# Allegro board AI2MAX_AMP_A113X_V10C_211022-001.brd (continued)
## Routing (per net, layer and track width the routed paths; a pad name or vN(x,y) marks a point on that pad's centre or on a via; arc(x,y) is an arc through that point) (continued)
NRST_AMP2: length 69.2
  TOP w0.1: v1(29.88,22.52) 29.27,23.12 29.27,27.02 29.6,27.35 29.6,36.5 29.15,36.95 29.15,39.65 v1(29.35,39.85) 29.15,40.05 29.15,46.95 29.6,47.4 v1(29.6,61.75)
  BOTTOM w0.1: v1(29.88,22.52) 30.18,22.52 32.66,25 34.9,25 36.35,26.45 38.5,26.45 R338.2 R315.2 R316.2
  BOTTOM w0.2: U302.36 26.87,58.72 27,58.85 27,59.67 27.42,60.09 C326.2 28.19,60.09 28.35,60.25 28.35,61.4 28.7,61.75 v1(29.6,61.75) ; U301.36 26.87,36.77 27,36.9 27,37.71 C304.2 28.19,38.14 28.35,38.3 28.35,39.4 28.8,39.85 v1(29.35,39.85)
OUT1A_B_LF: length 14
  TOP w0.5: v1(104.8,30.85) v1(104.2,30.85) ; v1(104.8,30.85) 104.8,27.7 ; v1(104.8,30.85) v1(104.8,31.45) 104.5,31.45 ; v1(104.2,30.85) 104.2,28.3 104.5,28 ; v1(104.2,30.85) v1(104.2,31.45) 104.5,31.45 ; 104.8,27.7 104.5,28 ; 104.8,27.7 105.9,26.6 ; 104.5,28 104.5,31.45
OUT1A_B_LW: length 16.6
  TOP w0.4: L211.2 L201.2
  TOP w0.5: 104.5,50 104.8,49.7 ; 104.5,50 104.2,50.3 v1(104.2,52.85) v1(104.2,53.45) 104.5,53.45 ; 104.5,50 104.5,53.45 ; 104.8,49.7 105.9,48.6 ; 104.8,49.7 v1(104.8,52.85) v1(104.8,53.45) 104.5,53.45
  BOTTOM w0.5: 102.9,52.2 C213.1 102.95,53.45
OUT1A_B_RF: length 13.3
  TOP w0.5: 12.2,57.47 v1(12.2,54.3) v1(12.2,53.7) 12.5,53.7 ; 12.2,57.47 11.15,58.52 ; 12.2,57.47 12.5,57.17 ; 12.5,53.7 v1(12.8,53.7) v1(12.8,54.3) 12.8,56.87 12.5,57.17 ; 12.5,53.7 12.5,57.17
OUT1A_B_RW: length 13.4
  TOP w0.5: 11.15,36.58 12.2,35.53 ; 12.2,35.53 v1(12.2,32.35) v1(12.2,31.75) 12.5,31.75 ; 12.2,35.53 12.5,35.23 ; 12.5,31.75 12.5,35.23 ; 12.5,31.75 v1(12.8,31.75) v1(12.8,32.35) 12.8,34.93 12.5,35.23
OUT2A_B_LF: length 13.3
  TOP w0.5: 104.7,36.4 104.8,36.3 v1(104.8,33.35) v1(104.8,32.75) 104.5,32.75 ; 104.7,36.4 104.5,36.2 ; 104.7,36.4 105.9,37.6 ; 104.5,36.2 104.2,35.9 v1(104.2,33.35) v1(104.2,32.75) 104.5,32.75 ; 104.5,36.2 104.5,32.75
OUT2A_B_LW: length 21.2
  TOP w0.5: 104.8,58.5 v1(104.8,55.35) v1(104.8,54.75) 104.5,54.75 ; 104.8,58.5 104.5,58.2 ; 104.8,58.5 105.9,59.6 ; 104.5,58.2 104.5,54.75 ; 104.5,58.2 104.2,57.9 v1(104.2,55.35) v1(104.2,54.75) 104.5,54.75
  BOTTOM w0.5: R205.1 C216.2 C213.2 102.95,54.75 v1(104.2,54.75) ; R205.1 104.2,55.9 v1(104.2,55.35) v1(104.2,54.75) ; R205.1 105,56 104.8,55.8 v1(104.8,55.35) v1(104.8,54.75) v1(104.2,54.75)
OUT2A_B_RF: length 15.4
  TOP w0.4: L304.2 L314.2
  TOP w0.5: 12.5,52.4 v1(12.2,52.4) v1(12.2,51.8) 12.2,48.6 ; 12.5,52.4 12.5,48.9 ; 12.5,52.4 v1(12.8,52.4) v1(12.8,51.8) 12.8,49.2 12.5,48.9 ; 12.5,48.9 12.2,48.6 ; 12.2,48.6 11.15,47.55
OUT2A_B_RW: length 13.4
  TOP w0.5: 12.5,30.45 v1(12.2,30.45) v1(12.2,29.85) 12.2,26.65 ; 12.5,30.45 12.5,26.95 ; 12.5,30.45 v1(12.8,30.45) v1(12.8,29.85) 12.8,27.25 12.5,26.95 ; 12.5,26.95 12.2,26.65 ; 11.15,25.6 12.2,26.65
PDM_DCLK: length 8.5
  TOP w0.1: U1.E16 67.86,48.49 68.4,48.49 68.58,48.31 73.15,48.31 73.49,48.65 74.8,48.65 T102.1
PDM_DIN0: length 9
  TOP w0.1: T103.1 75.85,48.45 73.65,48.45 73.3,48.1 68.49,48.1 68.42,48.17 U1.E17
PDM_DIN1: length 5.9
  TOP w0.1: T104.1 72.37,48.72 68.85,48.72 68.42,49.15 67.87,49.15 U1.D16
PDM_DIN2: length 6.4
  TOP w0.1: T105.1 73.75,49.25 73.01,48.51 68.73,48.51 68.43,48.82 U1.D17
PDM_DIN3: length 3.8
  TOP w0.1: U1.C17 68.46,49.47 68.98,48.95 71.3,48.95 T106.1
POWERSTB: length 67.2
  TOP w0.1: v1(36.75,58.05) 36.75,57.65 36.65,57.55 36.65,36.4 v1(36.85,36.2) ; v1(64.75,59.65) 65.15,59.25 65.15,57.15 v1(65.35,56.95)
  TOP w0.102: v2(64.62,49.15) U1.C12
  BOTTOM w0.1: v1(65.35,56.95) 65.5,56.8 65.5,51.22 64.93,50.65 64.93,49.46 v2(64.62,49.15) ; v1(36.75,58.05) 36.75,57.85 37.15,57.45 46.15,57.45 46.67,57.98 46.67,59.23 46.9,59.45 47.62,59.45 47.92,59.75 50.68,59.75 50.98,59.45 59.15,59.45 59.55,59.85 60.2,59.85 60.8,59.25 64.35,59.25 v1(64.75,59.65)
  BOTTOM w0.3: v1(36.85,36.2) 36.45,35.8 R12.1 R13.1
PVREF: length 0.5
  TOP w0.102: v2(63.97,43.29) U1.N11
PWR_24V: length 187.4
  TOP w0.5: 24.95,57.85 24.9,57.8 24.65,58.05 v1(24.65,58.65) v1(24.65,59.25) 24.95,59.25 ; 24.95,57.85 C355.1 ; 24.95,57.85 24.95,59.25 ; 24.95,57.85 25.25,58.15 v1(25.25,58.65) v1(25.25,59.25) 24.95,59.25 ; 24.95,46.83 v1(24.65,46.83) v1(24.65,47.43) 24.65,48.15 C348.1 24.95,48.35 ; 24.95,46.83 v1(25.25,46.83) v1(25.25,47.43) 25.25,48.05 24.95,48.35 ; 24.95,46.83 24.95,48.35 ; v1(23.4,17.8) v1(22.8,17.8) v1(22.8,17.2) ; v1(23.4,17.8) v1(22.8,17.2) ; v1(23.4,17.8) v1(24,17.8) ; 24.95,26.35 C354.1 ; 24.95,26.35 25.25,26.05 v1(25.25,25.48) v1(25.25,24.88) 24.95,24.88 ; 24.95,26.35 C324.1 24.65,26.15 v1(24.65,25.48) v1(24.65,24.88) 24.95,24.88 ; 24.95,26.35 24.95,24.88 ; 24.95,37.3 v1(24.65,37.3) v1(24.65,36.7) 24.65,36.05 24.9,35.8 24.95,35.85 ; 24.95,37.3 24.95,35.85 ; 24.95,37.3 v1(25.25,37.3) v1(25.25,36.7) 25.25,36.15 24.95,35.85 ; C248.1 91.8,37.1 v1(91.8,37.72) v1(91.8,38.32) 92.1,38.32 ; C248.1 92.1,38.32 ; C248.1 92.4,37.1 v1(92.4,37.72) v1(92.4,38.32) 92.1,38.32 ; C248.1 C258.1 ; v1(91.8,20.95) v1(92.4,20.95) ; v1(91.8,20.95) v1(92.4,20.35) ; v1(91.8,20.95) v1(91.2,20.95) ; v1(91.8,20.95) v1(91.2,21.55) ; v1(92.4,20.95) v1(91.8,21.55) ; v1(92.4,20.95) v1(92.4,21.55) v1(91.8,21.55) ; v1(92.4,20.95) v1(92.4,20.35) ; 92.1,27.4 91.8,27.1 v1(91.8,26.5) v1(91.8,25.9) 92.1,25.9 ; 92.1,27.4 92.1,25.9 ; 92.1,27.4 C257.1 ; 92.1,27.4 92.4,27.1 v1(92.4,26.5) v1(92.4,25.9) 92.1,25.9 ; 92.1,47.84 v1(91.8,47.84) v1(91.8,48.44) 91.8,49.1 92.1,49.4 ; 92.1,47.84 92.1,49.4 ; 92.1,47.84 v1(92.4,47.84) v1(92.4,48.44) 92.4,49.1 92.1,49.4 ; v1(22.8,17.2) v1(22.8,16.6) ; v1(92.4,20.35) v1(91.8,20.35) ; 24.95,48.35 C356.1 ; v1(22.8,16.6) v1(23.4,17.2) v1(24,17.8) ; v1(22.8,16.6) v1(23.4,16.6) ; v1(91.8,21.55) v1(91.2,21.55) ; 92.1,49.4 C255.1 ; C224.1 91.8,59.1 v1(91.8,59.66) v1(91.8,60.26) 92.1,60.26 ; C224.1 92.4,59.1 v1(92.4,59.66) v1(92.4,60.26) 92.1,60.26 ; C224.1 92.1,60.26 ; C224.1 C256.1 ; 24.95,35.85 C353.1 ; v1(91.2,20.95) v1(91.8,20.35) ; v1(91.2,20.95) v1(91.2,21.55) ; v1(91.2,20.95) v1(91.2,20.35) v1(91.8,20.35) ; v1(23.4,16.6) v1(24,16.6) v1(24,17.2) ; v1(23.4,16.6) v1(24,17.2) ; v1(24,17.8) v1(24,17.2)
  TOP w0.6: C4.1 12.87,10.12 U2.2
  BOTTOM w0.2: R1.2 v1(19.65,17)
  BOTTOM w0.3: 92.1,58.74 92.18,58.66 ; 92.18,58.66 92.18,57.69 ; 92.18,58.66 92.46,58.38 ; 24.6,56.68 24.87,56.68 ; 24.6,56.68 24.38,56.68 ; 24.6,56.68 24.6,57.35 24.59,57.37 ; 24.87,56.68 24.87,57.65 ; 24.87,56.68 U302.32 ; 24.59,57.37 24.87,57.65 ; 24.59,57.37 24.59,58.59 v1(24.65,58.65) ; 24.59,57.37 24.38,57.16 24.38,56.68 ; 24.87,57.65 24.95,57.73 ; 92.46,36.44 92.18,36.72 ; 92.46,36.44 92.67,36.23 92.67,35.75 ; 92.46,36.44 92.46,37.66 v1(92.4,37.72) ; 92.46,36.44 92.45,36.42 92.45,35.75 ; 92.18,36.72 92.18,35.75 ; 92.18,36.72 C248.1 ; 24.38,34.73 24.38,35.21 24.59,35.42 ; 24.38,34.73 24.37,34.72 U301.31 ; 24.38,34.73 24.6,34.73 ; 92.18,57.69 92.45,57.69 ; 92.18,57.69 U201.19 ; 24.59,48.71 24.38,48.92 24.38,49.4 ; 24.59,48.71 24.87,48.43 ; 24.59,48.71 24.59,47.49 v1(24.65,47.43) ; 24.59,48.71 24.6,48.73 24.6,49.4 ; 24.6,34.73 24.87,34.73 ; 24.6,34.73 24.6,35.4 24.59,35.42 ; 24.87,34.73 24.87,35.75 ; 24.87,34.73 U301.32 ; 92.18,49.5 C206.1 ; 92.18,49.5 92.4,49.72 92.46,49.72 ; 92.18,49.5 92.18,50.41 ; 24.95,48.35 C348.1 24.87,48.43 ; 24.6,27.45 24.87,27.45 ; 24.6,27.45 24.6,26.78 24.59,26.76 24.38,26.97 24.38,27.45 ; 24.6,27.45 24.38,27.45 ; 24.87,27.45 U301.19 ; 24.87,27.45 24.87,26.43 C324.1 ; 92.67,57.69 92.45,57.69 ; 92.67,57.69 92.68,57.68 U201.20 ; 92.67,57.69 92.67,58.17 92.46,58.38 ; 92.45,57.69 92.45,58.36 92.46,58.38 ; 92.46,58.38 92.46,59.6 v1(92.4,59.66) ; 24.59,35.42 24.59,35.47 24.87,35.75 ; 92.45,28.47 92.67,28.47 ; 92.45,28.47 92.45,27.8 92.46,27.78 ; 92.45,28.47 92.18,28.47 ; 92.67,28.47 92.67,27.99 92.46,27.78 ; 92.67,28.47 92.68,28.48 U202.31 ; 24.38,27.45 24.37,27.46 U301.20 ; U202.20 92.68,35.74 92.67,35.75 ; v1(92.4,26.5) 92.46,26.56 92.46,27.78 ; 24.6,49.4 24.87,49.4 ; 24.6,49.4 24.38,49.4 ; 24.87,49.4 24.87,48.43 ; 24.87,49.4 U302.19 ; 92.46,49.72 92.67,49.93 92.67,50.41 ; 92.46,49.72 92.45,49.74 92.45,50.41 ; 92.67,35.75 92.45,35.75 ; 92.45,35.75 92.18,35.75 ; 24.38,56.68 24.37,56.67 U302.31 ; 24.38,49.4 24.37,49.41 U302.20 ; 24.87,35.75 C306.1 ; 92.67,50.41 92.68,50.42 U201.31 ; 92.67,50.41 92.45,50.41 ; 92.18,28.47 U202.32 ; 92.18,28.47 92.18,27.5 ; 92.45,50.41 92.18,50.41 ; 92.18,50.41 U201.32 ; 92.46,27.78 92.18,27.5 ; 92.18,27.5 C231.1 ; 92.18,35.75 U202.19
  BOTTOM w0.5: v1(76.9,66.9) v1(77.5,66.3) ; v1(76.9,66.9) v1(76.3,67.5) ; v1(76.9,66.9) v1(76.9,67.5) ; v1(76.9,66.9) v1(76.9,66.3) ; v1(77.5,66.3) v1(77.5,66.9) ; v1(77.5,66.3) v1(77.5,65.7) ; v1(11.5,3.3) v1(11.5,2.7) v1(10.9,2.7) ; v1(11.5,3.3) v1(10.9,2.7) ; v1(11.5,3.3) v1(11.5,3.9) ; v1(24.65,47.43) v1(24.65,46.83) ; v1(24.65,47.43) v1(25.25,47.43) ; v1(24.65,47.43) 24.65,48.05 24.95,48.35 24.95,47.73 v1(25.25,47.43) ; v1(24.65,46.83) v1(25.25,46.83) v1(25.25,47.43) ; v1(24.65,46.83) v1(25.25,47.43) ; v1(10.9,3.3) v1(11.5,3.9) ; v1(10.9,3.3) v1(10.9,3.9) v1(11.5,3.9) ; v1(10.9,3.3) v1(10.9,2.7) ; v1(92.4,60.26) v1(91.8,60.26) v1(91.8,59.66) ; v1(92.4,60.26) v1(92.4,59.66) ; v1(92.4,60.26) v1(91.8,59.66) ; v1(24.65,58.65) v1(24.65,59.25) ; v1(24.65,58.65) v1(25.25,58.65) ; v1(24.65,58.65) 24.65,58.03 C331.1 24.95,57.73 24.95,58.35 v1(25.25,58.65) ; v1(24.65,59.25) v1(25.25,58.65) ; v1(24.65,59.25) v1(25.25,59.25) v1(25.25,58.65) ; v1(92.4,37.72) v1(92.4,38.32) ; v1(92.4,37.72) v1(91.8,37.72) ; v1(92.4,37.72) 92.4,37.1 C248.1 92.1,37.42 v1(91.8,37.72) ; v1(92.4,38.32) v1(91.8,37.72) ; v1(92.4,38.32) v1(91.8,38.32) v1(91.8,37.72) ; 24.65,36.03 C306.1 24.9,36.35 v1(25.25,36.7) ; 24.65,36.03 24.65,34.78 24.6,34.73 ; 24.65,36.03 v1(24.65,36.7) ; 43.8,68.85 v1(44.4,68.85) v1(44.4,68.25) ; 43.8,68.85 v1(44.4,68.25) ; 43.8,68.85 v1(43.75,68.85) v1(43.75,68.25) ; v1(76.3,67.5) v1(76.3,66.9) ; v1(76.3,67.5) v1(76.9,67.5) ; v1(76.9,67.5) v1(77.5,66.9) ; v1(76.9,67.5) v1(77.5,67.5) v1(77.5,66.9) ; v1(91.8,48.44) v1(92.4,48.44) ; v1(91.8,48.44) v1(91.8,47.84) v1(92.4,47.84) ; v1(91.8,48.44) v1(92.4,47.84) ; v1(91.8,48.44) 92.1,48.74 C206.1 ; v1(92.4,48.44) v1(92.4,47.84) ; v1(92.4,48.44) 92.4,49.9 92.45,49.95 ; v1(76.3,66.3) v1(76.9,65.7) ; v1(76.3,66.3) v1(76.3,65.7) ; v1(76.3,66.3) v1(76.3,66.9) ; v1(76.9,65.7) v1(76.9,65.1) ; v1(76.9,65.7) v1(76.9,66.3) ; v1(76.9,65.7) v1(77.5,65.1) ; v1(91.8,59.66) 92.1,59.36 C224.1 92.1,58.74 92.4,59.04 v1(92.4,59.66) ; v1(91.8,59.66) v1(92.4,59.66) ; v1(44.4,68.25) v1(44.4,67.6) ; v1(76.9,65.1) v1(76.3,65.1) v1(76.3,65.7) ; v1(76.9,65.1) v1(77.5,65.1) ; v1(76.9,65.1) v1(76.3,65.7) ; v1(76.9,66.3) v1(77.5,65.7) ; v1(76.9,66.3) v1(76.3,66.9) ; 43.8,67.6 43.75,67.65 v1(43.75,68.25) ; 43.8,67.6 v1(44.4,67.6) ; 43.8,67.6 v1(43.75,67.6) v1(43.75,67) v1(44.4,67) ; 43.8,67.6 v1(44.4,67) ; v1(44.4,67.6) v1(43.75,68.25) ; v1(44.4,67.6) v1(44.4,67) ; v1(77.5,65.1) v1(77.5,65.7) ; v1(25.25,36.7) v1(25.25,37.3) v1(24.65,37.3) ; v1(25.25,36.7) v1(24.65,37.3) ; v1(25.25,36.7) v1(24.65,36.7) ; v1(91.8,26.5) v1(92.4,25.9) ; v1(91.8,26.5) v1(91.8,25.9) v1(92.4,25.9) ; v1(91.8,26.5) 92.1,26.8 C231.1 92.4,27.12 v1(92.4,26.5) ; v1(91.8,26.5) v1(92.4,26.5) ; v1(92.4,25.9) v1(92.4,26.5) ; v1(25.25,25.48) v1(24.65,25.48) ; v1(25.25,25.48) v1(24.65,24.88) ; v1(25.25,25.48) v1(25.25,24.88) v1(24.65,24.88) ; v1(25.25,25.48) 24.95,25.78 24.95,26.35 C324.1 24.65,26.15 ; v1(24.65,25.48) 24.65,26.15 ; v1(24.65,25.48) v1(24.65,24.88) ; v1(24.65,37.3) v1(24.65,36.7) ; 24.65,26.15 24.65,27.05 24.6,27.1
  vias: v1(32.25,3.5) v1(32.25,2.9) v1(32.25,2.3) v1(32.85,3.5) v1(32.85,2.9) v1(32.85,2.3) v1(33.45,3.5) v1(33.45,2.9) v1(33.45,2.3) v1(59.95,5.65) v1(59.95,5.05) v1(59.95,4.45) v1(60.55,5.65) v1(60.55,5.05) v1(60.55,4.45) v1(61.15,5.65) v1(61.15,5.05) v1(61.15,4.45) v1(74.65,13.15) v1(74.65,12.55) v1(74.65,11.95) v1(74.65,11.35) v1(75.25,13.15) v1(75.25,12.55) v1(75.25,11.95) v1(75.25,11.35) v1(75.85,13.15) v1(75.85,12.55) v1(75.85,11.95) v1(75.85,11.35)
RMII_MDC: length 13.2
  TOP w0.1: U1.A11 64.29,50.91 63.96,51.25 63.96,55.05 64.75,55.84 64.75,56.5 64.47,56.77 63.88,56.77 63.7,56.95 63.7,59.95 64.3,60.55 64.8,60.55 v1(65.2,60.95)
  BOTTOM w0.4: v1(65.2,60.95) 66.03,60.95 T322.1
RMII_MDIO: length 15.5
  TOP w0.1: v1(65.9,62.3) 63.9,62.3 62.85,61.25 62.85,59.75 62.25,59.15 62.25,51.26 62.34,51.17 U1.A8
  BOTTOM w0.4: v1(65.9,62.3) 65.9,63.36 T323.1
RMII_RXCLK: length 15.2
  TOP w0.1: v1(61.77,62.48) 61.77,61.12 61.01,60.36 61.01,53.8 61.5,53.3 61.5,51.04 61.36,50.9 61.36,50.45 U1.B7
  BOTTOM w0.1: 62.8,63.5 v1(61.77,62.48)
  BOTTOM w0.4: T325.1 62.8,63.5
RMII_RXD0: length 17
  TOP w0.1: U1.B8 62.01,50.45 62.01,59.21 62.65,59.85 62.65,61.85 63.05,62.25 v1(63.05,62.45)
  BOTTOM w0.1: v1(63.05,62.45) 62.65,62.05 61,62.05 60.5,62.55 60.5,63.04
  BOTTOM w0.4: T327.1 60.5,63.04
RMII_RXD1: length 12.6
  TOP w0.1: U1.A6 61.04,50.94 61.22,51.12 61.22,52.97 60.25,53.95 60.25,60.1 v1(59.4,60.95)
  BOTTOM w0.4: T326.1 59.41,60.96 v1(59.4,60.95)
RMII_RXDV: length 11.3
  TOP w0.1: U1.A7 61.77,50.85 61.77,59.32 62.25,59.8 v1(62.25,60.25)
  BOTTOM w0.4: T324.1 62.96,60.96 v1(62.25,60.25)
RMII_TXD0: length 17.6
  TOP w0.1: v1(64.4,60.95) 63.49,60.04 63.49,51.07 63.64,50.92 U1.A10
  BOTTOM w0.1: 58.89,60.49 60.51,60.49 61.15,59.85 63.45,59.85 64.4,60.8 v1(64.4,60.95)
  BOTTOM w0.4: T328.1 58.89,60.49
RMII_TXD1: length 24.1
  TOP w0.1: v1(65.2,61.75) 64.8,61.35 64,61.35 63.25,60.6 63.25,50.95 63.32,50.88 63.32,49.8 62.99,49.47 U1.C9
  BOTTOM w0.1: v1(65.2,61.75) 64.8,61.35 64.25,61.35 63.95,61.65 60.2,61.65 59.85,62 57.38,62 56.72,62.66
  BOTTOM w0.4: T331.1 56.72,62.66
RMII_TXEN: length 20.2
  TOP w0.1: v1(64.4,61.75) 63.8,61.75 63.05,61 63.05,59.65 62.48,59.08 62.48,51.41 62.66,51.23 62.66,50.45 U1.B9
  BOTTOM w0.1: v1(64.4,61.75) 64.3,61.85 60.35,61.85 59.95,62.25 58.8,62.25 58.42,62.63
  BOTTOM w0.4: T329.1 58.42,62.63
SCL: length 8.3
  BOTTOM w0.1: J813.8 83.68,8.92 82.2,10.4 80.95,10.4 80.45,10.9 80.45,13.3 80.9,13.75 UNK5R66.1
SCL_AMP1: length 66.9
  TOP w0.1: R349.2 85.5,59.2 v1(85.35,59.05) 85.35,58.45 86,57.8 86,47.9 86.3,47.6 86.3,37.4 v1(85.95,37.05)
  BOTTOM w0.1: v1(85.35,59.05) 81.95,59.05 81.5,58.6 79.15,58.6 R238.2 78.25,58.6 73,58.6 72.8,58.8 67.6,58.8 67.05,59.35 66.47,59.35 65.77,58.65 64.6,58.65 64.4,58.85 52.95,58.85 51.85,57.75 R211.2
  BOTTOM w0.2: U201.11 88.18,57.2 87.4,57.2 87.15,57.45 87.15,58.43 C222.2 87.07,58.48 86.5,59.05 v1(85.35,59.05) ; v1(85.95,37.05) 86.68,37.05 C246.2 87.2,35.55 87.4,35.35 88.05,35.35 88.18,35.22 U202.11
SCL_AMP2: length 59.8
  TOP w0.1: v1(31.4,57.4) 31,57 31,56.6 31.2,56.4 31.2,48.55 v1(31.05,48.4) 31.25,48.2 31.25,39.35 30.85,38.95 30.85,37.4 31.25,37 31.25,26.3 v1(31.1,26.15) 31.3,25.95 R351.2 ; R309.2 v1(48.2,57.7)
  BOTTOM w0.1: v1(31.05,48.4) 30.06,48.4 C346.2 29.85,49.48 29.48,49.85 28.87,49.85 U302.11 ; R311.2 v1(48.2,57.7) 47.15,56.65 36.65,56.65 35.85,55.85 33.4,55.85 32.25,57 31.8,57 v1(31.4,57.4)
  BOTTOM w0.2: v1(31.1,26.15) 30.59,26.66 C322.2 29.85,27.5 29.4,27.95 28.87,27.95 U301.11
SDA: length 5.2
  BOTTOM w0.1: J813.7 84.18,8.72 82.3,10.6 81.15,10.6 80.9,10.85 UNK5R65.1
SDA_AMP1: length 69.4
  TOP w0.1: v1(85.35,35.95) 85.35,37.05 86.1,37.8 86.1,47.5 85.8,47.8 85.8,57.44 v1(85.35,57.89) 84.95,58.29 84.95,59.25 85.25,59.55 85.4,59.55 R348.2
  BOTTOM w0.1: v1(85.35,57.89) 85.35,58.25 84.75,58.85 82.1,58.85 81.65,58.4 79.15,58.4 R239.2 78.25,58.4 72.9,58.4 72.7,58.6 67.5,58.6 66.95,59.15 66.55,59.15 65.85,58.45 64.5,58.45 64.3,58.65 53.05,58.65 52.5,58.1 52.5,57.25 R212.2
  BOTTOM w0.2: U201.10 86.02,56.3 C217.2 85.35,56.85 v1(85.35,57.89) ; v1(85.35,35.95) 85.35,34.91 C241.2 86.02,34.36 U202.10
SDA_AMP2: length 58.3
  TOP w0.1: v1(48.2,56.6) R310.2 ; v1(31.4,56.8) 31.4,49.45 v1(31.65,49.2) 31.45,49 31.45,39.25 31.05,38.85 31.05,37.5 31.45,37.1 31.45,27.5 v1(31.7,27.25) 31.7,26.15 R350.2
  BOTTOM w0.1: v1(31.65,49.2) 31.65,50.28 C341.2 31.04,50.79 U302.10 ; R312.2 v1(48.2,56.6) 48.05,56.45 36.75,56.45 35.95,55.65 33.3,55.65 32.15,56.8 v1(31.4,56.8)
  BOTTOM w0.2: v1(31.7,27.25) 31.7,28.29 C317.2 31.03,28.84 U301.10
SPDIF_IN: length 7.2
  TOP w0.102: v2(66.57,48.5) U1.E14
  BOTTOM w0.1: T107.1 72.43,49.68 70.48,49.68 69.95,49.15 67.8,49.15 67.43,48.78 66.85,48.78 v2(66.57,48.5)
SPDIF_OUT: length 3.1
  TOP w0.102: U1.C16 67.87,49.8 68.45,49.8 68.62,49.63 T108.1
SPI_CLK: length 33.2
  TOP w0.102: v1(52.83,54.36) 52.53,54.66 v1(52.53,60.35) ; U1.C6 61.38,49.8 v2(61.36,49.8)
  BOTTOM w0.1: v1(52.53,60.35) 39.25,60.35 38.8,60.8 ; v1(52.83,54.36) 58.69,54.36 61.21,51.84 61.21,50.05 61.36,49.9 v2(61.36,49.8)
  BOTTOM w0.3: UNK2T16.1 38.8,60.8
SPI_MISO: length 33.4
  TOP w0.1: v1(50.95,60.95) 51.51,60.39 51.51,59.54
  TOP w0.102: v1(52.05,53.55) 51.51,54.09 51.51,59.54 ; U1.D6 60.71,49.15 v2(60.71,49.15)
  BOTTOM w0.1: v1(50.95,60.95) 50.75,60.75 41.55,60.75 41.2,61.1 41.2,62.8 ; v2(60.71,49.15) 61.01,49.44 61.01,51.53 59.14,53.39 53.46,53.39 53.3,53.55 v1(52.05,53.55)
  BOTTOM w0.3: UNK2T19.1 41.2,62.8
SPI_MOSI: length 31.6
  TOP w0.1: 51.95,53.95 52.2,53.95 52.6,53.55 v1(52.6,53.15)
  TOP w0.102: v1(51.55,60.95) 51.71,60.79 51.71,54.19 51.95,53.95 ; U1.C5 60.65,49.73 v2(60.65,49.74)
  BOTTOM w0.1: v1(51.55,60.95) 51.15,60.55 41.05,60.55 40.71,60.89 ; v1(52.6,53.15) 59.07,53.15 60.81,51.41 60.81,49.89 v2(60.65,49.74)
  BOTTOM w0.3: UNK2T18.1 40.71,60.89
SPI_SS0: length 28.1
  TOP w0.1: U1.C1 57.64,49.47 56.79,50.32 56.79,50.9 55.37,52.33 55.37,53.14 54.6,53.91 54.6,57.1 54.26,57.44 54.26,62.43 53.7,62.99 v1(53.7,63.1)
  BOTTOM w0.1: v1(53.7,63.1) 53.3,63.5 52.7,63.5 51.9,62.7 43.1,62.7 42.8,62.4
  BOTTOM w0.3: UNK2T20.1 42.8,62.4
SPK_I2C_SCK: length 24.1
  TOP w0.1: v1(48.95,61.9) 49.85,61 49.85,59.8 50.35,59.3 v1(50.35,57.7) 49.95,57.3 49.95,56.4 50.55,55.8 50.55,53.05 51.35,52.25 53.9,52.25 54.53,51.62 55.16,51.62 56.18,50.6 56.18,49.99 57.68,48.49 58.77,48.49 U1.E3
  BOTTOM w0.1: R211.1 v1(50.35,57.7) R311.1 UNK2R18.2
  BOTTOM w0.3: UNK2T26.1 48.65,61.6 v1(48.95,61.9)
SPK_I2C_SDA: length 23.4
  TOP w0.1: v1(50.7,63.3) 50.05,62.65 50.05,59.9 50.75,59.2 50.75,57 v1(50.35,56.6) 50.77,56.18 50.77,53.14 51.45,52.45 54,52.45 54.61,51.84 55.25,51.84 56.39,50.7 56.39,50.09 57.66,48.82 U1.D1
  BOTTOM w0.1: R212.1 v1(50.35,56.6) R312.1 UNK2R19.2
  BOTTOM w0.3: v1(50.7,63.3) 50.3,63.3 UNK2T27.1
SPK_RST: length 13.9
  TOP w0.102: U1.C15 67.21,49.79 67.21,50.27 67.38,50.45 67.71,50.45 67.87,50.6 67.87,51.72 70.71,54.56 72.5,54.56 v2(72.62,54.68) ; v2(70.86,56.95) 70.86,57.76 71.53,58.42 UNK2T8.1
  BOTTOM w0.1: v2(70.86,56.95) 72.62,55.2 v2(72.62,54.68)
STANDBY_A113X: length 66.3
  TOP w0.1: v1(66.75,56.95) v2(66.75,58.78) ; v1(81.9,54.5) 82.25,54.15 82.25,48.55 82.5,48.3 82.5,33.75 83.3,32.95 83.3,20.95 v1(83.75,20.5)
  TOP w0.102: U1.C13 65.59,49.47 v2(65.3,49.76)
  BOTTOM w0.1: v1(66.75,56.95) 66.7,56.95 65.73,55.98 65.73,50.99 65.3,50.56 v2(65.3,49.76) ; UNK5R77.2 82,18.55 82.75,19.3 83.8,19.3 84.15,19.65 84.15,20.1 v1(83.75,20.5) ; v1(81.9,54.5) 80.8,55.6 74.4,55.6 71.6,58.4 67.13,58.4 v2(66.75,58.78)
SYS_LED: length 20.7
  TOP w0.1: v1(64.7,63.5) UNK2R8.2
  TOP w0.102: U1.A15 66.95,50.83 66.95,51.72 68.88,53.65 68.88,54.76 70.45,56.33 70.45,57.96 70.87,58.37 70.87,60.5 69.75,61.62 v1(69.75,62)
  BOTTOM w0.3: v1(69.75,62) 69.45,62.3 68.5,62.3 66.45,64.35 65.55,64.35 v1(64.7,63.5)
USB_PWR_EN: length 16.4
  TOP w0.102: UNK2T7.1 70.2,60.1 69.64,59.54 69.64,57.66 v2(69.8,57.51) ; v2(64.56,49.75) 64.55,49.74 64.55,49.73 U1.C11
  BOTTOM w0.1: v2(64.56,49.75) 64.56,51.49 64.95,51.87 64.95,54.85 64.65,55.15 64.65,55.5 64.97,55.83 64.97,57.48 65.17,57.67 69.63,57.67 v2(69.8,57.51)
USB_TXRTUNE: length 5.4
  TOP w0.102: v2(66.57,45.24) 66.57,45.25 U1.J15
  BOTTOM w0.1: v2(66.57,45.24) 66.89,45.57 68.81,45.57 68.96,45.72 69.67,45.72 69.85,45.54 69.85,45.39 UNK5R64.1
USBOTG_A_DM: length 45.2
  TOP w0.1: U1.L16 67.77,44.27 68.09,43.95 68.96,43.95 69.39,43.52 69.72,43.52 70.88,42.37 70.88,41.06 72.38,39.56 72.38,37.46 73.15,36.68 73.15,22.7 77.8,18.05 80.16,18.05 81.64,16.57 84.42,16.57 v1(84.65,16.35) 85.1,16.35 UNK5R84.2
  BOTTOM w0.1: v1(84.65,16.35) 85.55,15.45 UNK5D12.1 85.55,14.15 85.45,14.05 84.85,14.05 84.75,13.95 84.75,13.55 85.15,13.15 85.15,12.55 85.55,12.15 UNK5R71.2
USBOTG_A_DP: length 45.3
  TOP w0.1: U1.L17 68.28,44.17 69.06,44.17 69.48,43.75 69.82,43.75 71.1,42.47 71.1,41.15 72.6,39.65 72.6,37.55 73.38,36.77 73.38,22.79 77.89,18.27 80.26,18.27 81.73,16.8 84.35,16.8 v1(84.65,17.1) 85.05,17.1 UNK5R85.2
  BOTTOM w0.1: v1(84.65,17.1) 84.2,16.65 84.2,15 83.75,14.55 UNK5D11.1 83.75,14.15 83.85,14.05 84.45,14.05 84.53,13.97 84.53,13.46 84.92,13.06 84.92,12.52 84.55,12.15 UNK5R72.2
USBOTG_A_ID: length 39.4
  TOP w0.1: UNK5R83.2 81.95,18.2 v1(81.55,18.6) 80.8,19.35 78.35,19.35 75.1,22.6 75.1,29.35 75.85,30.1 75.85,39 v1(74.15,40.7) UNK5R78.1 UNK5C3.2 73.95,42.55 73.35,43.15 73.35,43.8 72.88,44.27 69.7,44.27 69.29,44.68 68.61,44.68 68.37,44.92 U1.K17
  BOTTOM w0.1: v1(81.55,18.6) 80.9,17.95 UNK5R76.2
  BOTTOM w0.3: UNK5R20.2 74.4,40.7 v1(74.15,40.7)
USBOTG_A_VBUS: length 7
  TOP w0.1: U1.K16 67.86,44.6 68.35,44.6 68.51,44.44 69.17,44.44 69.57,44.05 72.2,44.05 UNK5C11.2
  TOP w0.3: UNK5R5.2 UNK5C11.2
WPN: length 3.3
  TOP w0.1: v1(47.15,30.2) 47.14,30.21 UNK4U5.19
  BOTTOM w0.1: v1(47.15,30.2) UNK4C9.2 UNK4R4.2
N21450221: length 2.7
  BOTTOM w0.3: Q1.1 34.2,32.35 C23.1 R13.2
N21455517: length 0.8
  TOP w0.3: U1.F13 v2(65.27,47.2)
  BOTTOM w0.2: v2(65.27,47.2) 65.05,46.98 UNK2R27.1
N21455804: length 4.3
  TOP w0.102: v2(67.14,48.43) 67.14,48.42 U1.E15
  BOTTOM w0.3: UNK2R29.1 70.5,48.75 67.85,48.75 67.53,48.43 v2(67.14,48.43)
N21455846: length 2.7
  TOP w0.1: UNK2R12.2 59.55,61.95 UNK2Q1.3
N21455854: length 1.8
  TOP w0.1: UNK2D7.2 56.1,62.85 UNK2R12.1
N21456017: length 6.3
  TOP w0.102: U1.D11 63.98,49.15 v2(63.97,49.15)
  BOTTOM w0.1: UNK2T29.1 63.24,53.69 63.24,52.29 63.93,51.6 63.93,50.4 63.6,50.07 63.6,49.36 63.82,49.15 v2(63.97,49.15)
N21456060: length 7.4
  TOP w0.127: 68.4,50.47 68.38,50.45 68.05,50.45 67.72,50.12 U1.B16
  TOP w0.2: UNK2Y2.1 73.14,50.4 71.9,50.4 71.36,50.94 UNK2C3.2 71.28,51.06 UNK2R5.1 69.59,50.47 68.4,50.47
N21456068: length 4.4
  TOP w0.2: UNK2R10.2 70.48,53.21 69.52,52.25 69.52,51.14 69.23,50.85 68.27,50.85 U1.A17
N21456125: length 7.6
  TOP w0.2: UNK2Y2.3 75.17,53.95 73.26,53.95 72.52,53.21 UNK2R10.1 71.85,52.61 UNK2C9.2 70.34,52.12 UNK2R5.2
N21456352: length 6.9
  TOP w0.1: UNK2R1.1 59.96,68.99 UNK2CON1.4
N21456391: length 6.4
  TOP w0.1: UNK2CON1.2 58.84,70.05 UNK2R16.1
N21464427: length 1
  TOP w0.102: U1.N8 62.6,43.23 v2(62.6,43.23)
  BOTTOM w0.102: v2(62.6,43.23) 62.84,43.23 UNK3R6.2
N21467829: length 7.5
  TOP w0.1: U1.M3 59.09,43.62 v2(58.76,43.94)
  BOTTOM w0.102: UNK4T25.1 53.4,41.1 54,41.1 54.7,41.8 55.4,41.8 56.71,43.11 57.46,43.11 58.29,43.94 v2(58.76,43.94)
N21468142: length 76.3
  TOP w0.1: v1(38.15,27.05) 37.65,27.05 36.85,27.85 36.85,33.6 37.5,34.25 37.5,36.45 37.05,36.9 37.05,52.45 v1(37.25,52.65) ; v1(39.45,54) 39.58,54 UNK4R10.1 ; v1(8.7,16.1) 8.7,14.32 7.47,13.1 UNK4K2.4 UNK4K2.3
  BOTTOM w0.1: v1(37.25,52.65) 37.25,52.8 38.45,54 v1(39.45,54) ; v1(38.15,27.05) 37.75,26.65 36.05,26.65 34.6,25.2 32.55,25.2 30.3,22.95 29.05,22.95 28.65,22.55 28.65,21.15 26.95,19.45 15.4,19.45 14.75,20.1 13.35,20.1 12.25,19 10.3,19 8.7,17.4 v1(8.7,16.1)
N21476089: length 7.5
  TOP w0.1: U1.J16 67.88,45.23 68.43,45.23 68.67,44.99 73.01,44.99 74.15,43.85 R101.1
N21476146: length 7
  TOP w0.102: U1.H17 69,46.22 69.19,46.03 74.88,46.03 R102.1
N21492341: length 4.6
  BOTTOM w0.2: R54.2 R337.1 C65.2 49.32,9.78 U51.4
N21492347: length 2
  BOTTOM w0.5: C53.1 52.6,12.59 52.6,11.82
N21492451: length 4.8
  BOTTOM w0.2: R59.2 R55.1 R51.1 C63.1 U51.3
N21492734: length 2
  BOTTOM w0.2: C66.2 R56.1 R55.2
N21494202: length 4.7
  BOTTOM w0.5: R334.2 R335.2 C78.1 U54.1
N21494218: length 3.6
  BOTTOM w0.1: R331.1 R336.2 U54.3
N21499562: length 4
  TOP w0.5: 41.1,11.82 40.25,12.67 C59.2 40.25,15.36 40.2,15.41
N21499612: length 2.1
  TOP w0.3: U52.4 42.6,9.78 R52.1
N21499616: length 2
  TOP w0.5: C59.1 38.5,12.59 38.5,11.82
N21499652: length 5.3
  TOP w0.2: R60.2 R57.1 C64.1 R53.1 38.7,9.57 U52.3
N21499757: length 2.1
  TOP w0.2: C67.2 41.75,6.95 R57.2 R58.1
N21500929: length 4
  TOP w0.5: 50.9,15.41 50.95,15.36 C70.2 50.95,12.67 51.8,11.82
N21500979: length 3.2
  TOP w0.2: R62.2 C75.2 53.28,9.78 U53.4
N21500983: length 2
  TOP w0.5: 49.2,11.82 50.05,12.67 C70.1
N21501019: length 3.7
  TOP w0.2: R63.2 R61.1 C74.1 U53.3
N21506141: length 6.5
  TOP w0.2: U3.4 31.78,9.01 32.81,7.99 C20.2 ; C20.2 32.76,6.99 R7.2 ; C20.2 R6.1 33.86,6.99 R19.1
N21506145: length 2
  TOP w0.5: C15.1 28.21,11.83 U3.1
N21506181: length 3.7
  TOP w0.2: C19.1 R8.1 R9.2 U3.3
N21534101: length 1.4
  TOP w0.1: v2(63.25,27.54) 62.85,27.14 UNK3U1.L8
  BOTTOM w0.102: v2(63.25,27.54) 63.42,27.37 UNK3R10.2
N21597998: length 1.7
  TOP w0.1: UNK2Q1.1 UNK2R8.1
N21714583: length 39.7
  TOP w0.4: L211.1 L201.1
  TOP w0.5: 95.15,47.25 95.45,47.55 ; 95.15,47.25 95.15,45.39 ; 95.15,47.25 94.85,46.95 v1(94.85,45.99) v1(94.85,45.39) 95.15,45.39 ; 95.45,47.55 v1(95.45,45.99) v1(95.45,45.39) 95.15,45.39 ; 95.45,47.55 96.5,48.6
  BOTTOM w0.3: C210.1 95.28,51.8 U201.30 ; C202.2 91.18,48.74 91.45,49.01 91.45,50.5 91.68,50.73 U201.33
  BOTTOM w0.5: R203.1 95.27,51.73 C210.1 ; R203.1 95.27,47.75 ; R203.1 95.45,49.6 95.45,47.57 ; v1(94.85,45.99) 94.85,46.35 ; v1(94.85,45.99) v1(95.45,45.99) ; v1(94.85,45.99) v1(94.85,45.39) 95.15,45.39 ; 94.85,46.35 94.85,46.75 94.56,47.04 ; 94.85,46.35 94.45,46.75 91.6,46.75 ; 95.27,47.75 95.15,47.63 ; 95.27,47.75 95.45,47.57 ; 91.6,46.75 91.45,46.9 91.59,47.04 94.56,47.04 ; 91.6,46.75 91.35,46.75 R202.2 90.84,47.26 C202.2 ; 95.15,47.63 94.56,47.04 ; 95.15,47.63 95.15,45.39 ; 95.15,45.39 v1(95.45,45.39) v1(95.45,45.99) ; 95.45,47.57 v1(95.45,45.99)
N21714609: length 5.8
  BOTTOM w0.2: U201.38 89.18,50.68 88.9,50.4 88.9,48.1 87.8,47 C251.2 R227.2
N21714673: length 1.5
  BOTTOM w0.5: C203.2 R202.1
N21714680: length 1.6
  BOTTOM w0.3: U201.35 90.68,49.8 C202.1
N21714717: length 1.5
  BOTTOM w0.2: U201.37 89.68,49.7 R201.1
N21714779: length 1.3
  BOTTOM w0.5: R203.2 C207.2
N21714803: length 1.6
  BOTTOM w0.3: U201.2 86.09,52.3 C208.2
N21714950: length 2
  BOTTOM w0.3: U201.28 95.18,52.8 C210.2
N21714966: length 3.4
  BOTTOM w0.3: U201.27 96.38,53.3 C211.1
N21715014: length 1.7
  BOTTOM w0.3: C218.1 85.9,54.3 U201.6
N21715038: length 3.4
  BOTTOM w0.3: U201.24 96.38,54.8 96.64,55.06 C214.1
N21715056: length 2
  BOTTOM w0.3: U201.23 95.18,55.3 C215.2
N21715058: length 45
  TOP w0.4: L212.1 L202.1
  TOP w0.5: 95.15,60.95 94.85,61.25 v1(94.85,62.21) v1(94.85,62.81) 95.15,62.81 ; 95.15,60.95 95.45,60.65 ; 95.15,60.95 95.15,62.81 ; 95.45,60.65 96.5,59.6 ; 95.45,60.65 v1(95.45,62.21) v1(95.45,62.81) 95.15,62.81
  BOTTOM w0.3: C215.1 95.28,56.3 U201.21 ; U201.18 91.68,57.37 91.45,57.6 91.45,59.09 91.16,59.38 C220.1
  BOTTOM w0.5: R208.1 90.84,60.99 C220.1 ; R208.1 94.85,61.8 ; R208.1 91.65,62.25 94.29,62.25 94.47,62.43 ; R208.1 92.1,61.35 94.27,61.35 ; R206.2 95.27,56.37 C215.1 ; R206.2 95.27,60.35 ; R206.2 95.45,58.5 95.45,60.53 ; 95.27,60.35 95.15,60.47 ; 95.27,60.35 95.45,60.53 ; 95.45,60.53 v1(95.45,62.21) ; v1(94.85,62.81) v1(94.85,62.21) ; v1(94.85,62.81) 95.15,62.81 ; v1(94.85,62.81) 94.47,62.43 ; v1(94.85,62.21) v1(95.45,62.21) ; v1(94.85,62.21) 94.85,61.8 ; 94.56,61.06 94.27,61.35 ; 94.56,61.06 95.15,60.47 ; 94.56,61.06 94.85,61.35 94.85,61.8 ; 94.27,61.35 94.47,61.55 94.47,62.43 ; v1(95.45,62.21) v1(95.45,62.81) 95.15,62.81 ; 95.15,62.81 95.15,60.47
N21715192: length 1.3
  BOTTOM w0.5: R206.1 C219.2
N21715198: length 4.2
  BOTTOM w0.2: T201.1 88,60.05 88,59.14 89.18,57.96 U201.13
N21715200: length 1.6
  BOTTOM w0.2: U201.14 89.68,58.42 R207.2
N21715202: length 4.3
  BOTTOM w0.2: T202.1 89.49,60.45 90.18,59.76 U201.15
N21715204: length 1.6
  BOTTOM w0.3: C220.2 90.68,58.32 U201.16
N21715315: length 1.3
  BOTTOM w0.4: C221.2 R208.2
N21715441: length 40.2
  TOP w0.4: L203.1 L213.1
  TOP w0.5: 95.15,23.45 95.15,25.25 ; 95.15,23.45 v1(95.45,23.45) v1(95.45,24.05) ; 95.15,23.45 v1(94.85,23.45) v1(94.85,24.05) ; 95.15,25.25 94.85,24.95 v1(94.85,24.05) ; 95.15,25.25 95.45,25.55 ; v1(95.45,24.05) v1(94.85,24.05) ; v1(95.45,24.05) 95.45,25.55 ; 95.45,25.55 96.5,26.6
  BOTTOM w0.3: C225.2 91.18,26.8 91.45,27.07 91.45,28.55 91.68,28.78 U202.33 ; C234.1 95.28,29.86 U202.30
  BOTTOM w0.5: v1(95.45,24.05) 95.45,25.63 ; v1(95.45,24.05) v1(95.45,23.45) 95.15,23.45 ; v1(95.45,24.05) v1(94.85,24.05) ; 95.45,25.63 95.45,27.66 R217.1 ; 95.45,25.63 95.27,25.81 ; R213.2 91.3,24.8 94.5,24.8 94.85,24.45 ; R213.2 90.84,25.26 C225.2 ; R213.2 91.3,25.1 94.56,25.1 ; C234.1 95.27,29.79 R217.1 ; 95.27,25.81 R217.1 ; 95.27,25.81 95.15,25.69 ; 95.15,23.45 v1(94.85,23.45) v1(94.85,24.05) ; 95.15,23.45 95.15,25.69 ; 94.85,24.45 v1(94.85,24.05) ; 94.85,24.45 94.85,24.81 94.56,25.1 ; 95.15,25.69 94.56,25.1
N21715461: length 5.8
  BOTTOM w0.2: U202.38 89.18,28.2 88.9,27.92 88.9,26.16 C253.2 R229.2
N21715523: length 1.5
  BOTTOM w0.5: C228.2 R213.1
N21715527: length 1.6
  BOTTOM w0.3: U202.35 90.68,27.86 C225.1
N21715561: length 1.5
  BOTTOM w0.2: R214.1 89.68,27.76 U202.37
N21715623: length 1.3
  BOTTOM w0.5: R217.2 C229.2
N21715647: length 1.6
  BOTTOM w0.3: U202.2 86.09,30.36 C232.2
N21715792: length 2
  BOTTOM w0.3: C234.2 95.18,30.86 U202.28
N21715808: length 3.4
  BOTTOM w0.3: C235.1 96.37,31.36 U202.27
N21715856: length 1.7
  BOTTOM w0.3: C242.1 85.9,32.36 U202.6
N21715880: length 3.4
  BOTTOM w0.3: C238.1 96.38,32.86 U202.24
N21715898: length 2
  BOTTOM w0.3: U202.23 95.19,33.36 C239.2
N21715900: length 40.9
  TOP w0.4: L204.1 L214.1
  TOP w0.5: 95.45,38.65 v1(95.45,40.16) v1(95.45,40.76) 95.15,40.76 ; 95.45,38.65 95.15,38.95 ; 95.45,38.65 96.5,37.6 ; 95.15,38.95 95.15,40.76 ; 95.15,38.95 94.85,39.25 v1(94.85,40.16) v1(94.85,40.76) 95.15,40.76
  BOTTOM w0.3: C239.1 95.29,34.36 U202.21 ; U202.18 91.68,35.42 91.45,35.65 91.45,37.15 91.17,37.43 C244.1
  BOTTOM w0.5: R222.2 95.27,34.42 C239.1 ; R222.2 95.27,38.4 ; R222.2 95.45,36.55 95.45,38.58 ; v1(95.45,40.16) v1(95.45,40.76) 95.15,40.76 ; v1(95.45,40.16) v1(94.85,40.16) ; v1(95.45,40.16) 95.45,38.58 ; v1(94.85,40.16) v1(94.85,40.76) 95.15,40.76 ; v1(94.85,40.16) 94.14,39.45 ; v1(94.85,40.16) 94.85,39.4 ; 94.14,39.45 91.4,39.45 R224.1 ; 94.14,39.45 94.22,39.45 ; 95.27,38.4 95.15,38.52 ; 95.27,38.4 95.45,38.58 ; 94.22,39.45 94.8,39.45 94.85,39.4 ; 94.22,39.45 94.52,39.15 ; 94.85,39.4 94.56,39.11 ; 94.56,39.11 94.52,39.15 ; 94.56,39.11 95.15,38.52 ; 95.15,40.76 95.15,38.52 ; C244.1 90.84,38.89 R224.1 ; 94.52,39.15 91.25,39.15 R224.1
N21716032: length 1.3
  BOTTOM w0.5: R222.1 C243.2
N21716038: length 4.5
  BOTTOM w0.2: U202.13 89.18,36.02 88.9,36.3 88.9,38.11 T203.1
N21716040: length 1.5
  BOTTOM w0.2: U202.14 89.68,36.47 R223.2
N21716042: length 4.2
  BOTTOM w0.2: U202.15 90.18,37.82 90.05,37.95 90.05,38.59 T204.1
N21716044: length 1.6
  BOTTOM w0.3: U202.16 90.68,36.37 C244.2
N21716155: length 1.5
  BOTTOM w0.5: C245.2 R224.2
N21722582: length 41.8
  TOP w0.4: L301.1 L311.1
  TOP w0.5: 21.6,37.63 20.55,36.58 ; 21.6,37.63 v1(21.6,39.15) v1(21.6,39.75) 21.9,39.75 ; 21.6,37.63 21.9,37.93 ; 21.9,39.75 v1(22.2,39.75) v1(22.2,39.15) 22.2,38.23 21.9,37.93 ; 21.9,39.75 21.9,37.93
  BOTTOM w0.3: U301.30 21.77,33.34 C310.1 ; C302.2 25.87,36.4 25.6,36.13 25.6,34.65 25.37,34.42 U301.33
  BOTTOM w0.5: 26.21,37.44 25.55,38.1 23.9,38.1 ; 26.21,37.44 26.21,37.89 R302.2 25.75,38.35 24.15,38.35 ; 26.21,37.44 C302.2 ; 23.9,38.1 24.15,38.35 ; 23.9,38.1 22.49,38.1 ; 24.15,38.35 23,38.35 22.7,38.65 ; 21.9,39.75 v1(22.2,39.75) v1(22.2,39.15) ; 21.9,39.75 v1(21.6,39.75) v1(21.6,39.15) ; 21.9,39.75 21.9,37.85 ; 22.7,38.65 21.9,37.85 ; 22.7,38.65 v1(22.2,39.15) ; R303.1 21.78,33.41 C310.1 ; R303.1 21.78,37.39 ; R303.1 21.6,35.54 21.6,37.57 ; v1(22.2,39.15) 22.2,38.39 22.49,38.1 ; v1(22.2,39.15) v1(21.6,39.15) ; v1(21.6,39.15) 21.6,37.57 ; 21.9,37.85 21.9,37.51 ; 21.78,37.39 21.6,37.57 ; 21.78,37.39 21.9,37.51 ; 22.49,38.1 21.9,37.51
N21722605: length 5.8
  BOTTOM w0.2: R325.2 30.34,38.14 C349.2 28.15,37.03 28.15,35.28 27.87,35 U301.38
N21722669: length 1.5
  BOTTOM w0.5: C303.2 R302.1
N21722673: length 1.6
  BOTTOM w0.3: C302.1 26.37,35.34 U301.35
N21722707: length 1.5
  BOTTOM w0.2: R301.1 27.37,35.44 U301.37
N21722769: length 1.3
  BOTTOM w0.5: R303.2 C307.2
N21722793: length 1.6
  BOTTOM w0.3: C308.2 30.97,32.84 U301.2
N21722936: length 2
  BOTTOM w0.3: C310.2 21.87,32.34 U301.28
N21722954: length 3.4
  BOTTOM w0.3: C311.1 20.68,31.84 U301.27
N21722998: length 1.7
  BOTTOM w0.3: U301.6 31.15,30.84 C318.1
N21723019: length 3.4
  BOTTOM w0.3: U301.24 20.68,30.34 C314.1
N21723038: length 2
  BOTTOM w0.3: C315.2 21.87,29.84 U301.23
N21723040: length 40.9
  TOP w0.4: L312.1 L302.1
  TOP w0.5: 21.9,22.43 21.9,24.25 ; 21.9,22.43 v1(22.2,22.43) v1(22.2,23.03) 22.2,23.95 21.9,24.25 ; 21.9,22.43 v1(21.6,22.43) v1(21.6,23.03) 21.6,24.55 ; 21.9,24.25 21.6,24.55 ; 21.6,24.55 20.55,25.6
  BOTTOM w0.3: U301.18 25.37,27.73 25.6,27.5 25.6,26.05 25.89,25.76 C320.1 ; U301.21 21.77,28.84 C315.1
  BOTTOM w0.5: v1(21.6,23.03) 21.6,24.61 ; v1(21.6,23.03) v1(21.6,22.43) ; v1(21.6,23.03) 21.9,23.03 ; 21.6,24.61 21.6,26.64 R306.2 ; 21.6,24.61 21.78,24.79 ; v1(21.6,22.43) v1(22.2,23.03) ; v1(21.6,22.43) v1(22.2,22.43) v1(22.2,23.03) ; 22.63,23.66 22.24,23.66 21.9,24 ; 22.63,23.66 22.77,23.8 ; 22.63,23.66 22.2,23.23 v1(22.2,23.03) ; 21.78,24.79 21.9,24.67 ; 21.78,24.79 R306.2 ; 21.9,24.67 21.9,24 ; 21.9,24.67 22.49,24.08 23.05,24.08 ; 26.21,24.74 25.55,24.08 23.05,24.08 ; 26.21,24.74 C320.1 ; 26.21,24.74 26.21,24.31 R308.1 25.85,23.8 22.77,23.8 ; v1(22.2,23.03) 21.9,23.03 ; 23.05,24.08 22.77,23.8 ; 21.9,23.03 21.9,24 ; C315.1 21.74,26.86 R306.2
N21723161: length 1.3
  BOTTOM w0.5: R306.1 C319.2
N21723167: length 4.5
  BOTTOM w0.2: U301.13 27.87,27.18 28.15,26.9 28.15,25.08 T301.1
N21723169: length 1.6
  BOTTOM w0.2: R307.2 27.37,26.72 U301.14
N21723171: length 4.2
  BOTTOM w0.2: T302.1 27,24.6 27,25.25 26.87,25.38 U301.15
N21723173: length 1.6
  BOTTOM w0.3: C320.2 26.37,26.82 U301.16
N21723285: length 1.5
  BOTTOM w0.5: C321.2 R308.2
N21723494: length 41.9
  TOP w0.4: L313.1 L303.1
  TOP w0.5: 21.9,61.7 v1(21.6,61.7) v1(21.6,61.1) 21.6,59.57 ; 21.9,61.7 v1(22.2,61.7) v1(22.2,61.1) 22.2,60.17 21.9,59.87 ; 21.9,61.7 21.9,59.87 ; 21.9,59.87 21.6,59.57 ; 21.6,59.57 20.55,58.52
  BOTTOM w0.3: C334.1 21.76,55.29 U302.30 ; C325.2 25.87,58.35 25.6,58.08 25.6,56.65 25.37,56.42 U302.33
  BOTTOM w0.5: R317.1 21.78,55.35 C334.1 ; R317.1 21.78,59.33 ; R317.1 21.6,57.48 21.6,59.52 ; 22.54,60.76 v1(22.2,61.1) ; 22.54,60.76 22.54,60 ; 22.54,60.76 23,60.3 23.9,60.3 ; v1(22.2,61.1) v1(21.6,61.1) ; v1(22.2,61.1) 22.2,60.34 22.49,60.05 ; v1(22.2,61.1) v1(22.2,61.7) 21.9,61.7 ; v1(21.6,61.1) v1(21.6,61.7) 21.9,61.7 ; v1(21.6,61.1) 21.6,59.52 ; 21.9,61.7 21.9,59.45 21.78,59.33 ; 22.54,60 23.6,60 ; 22.54,60 22.49,60.05 ; 23.6,60 25.6,60 26.21,59.39 ; 23.6,60 23.9,60.3 ; 23.9,60.3 25.95,60.3 R313.2 26.21,59.89 26.21,59.39 ; 21.78,59.33 21.78,59.34 ; 26.21,59.39 C325.2 ; 21.6,59.52 21.78,59.34 ; 21.78,59.34 22.49,60.05
N21723515: length 5.8
  BOTTOM w0.2: U302.38 27.87,56.95 28.15,57.23 28.15,58.98 C351.2 29.27,60.1 R327.2
N21723601: length 1.6
  BOTTOM w0.5: C328.2 R313.1
N21723605: length 1.6
  BOTTOM w0.3: C325.1 26.37,57.29 U302.35
N21723639: length 1.5
  BOTTOM w0.2: U302.37 27.37,57.39 R314.1
N21723713: length 1.3
  BOTTOM w0.5: C329.2 R317.2
N21723762: length 1.6
  BOTTOM w0.3: C332.2 30.98,54.79 U302.2
N21723903: length 2
  BOTTOM w0.3: U302.28 21.86,54.29 C334.2
N21723921: length 3.4
  BOTTOM w0.3: C335.1 20.67,53.79 U302.27
N21723965: length 1.7
  BOTTOM w0.3: U302.6 31.16,52.79 C342.1
N21723986: length 3.4
  BOTTOM w0.3: U302.24 20.68,52.29 C338.1
N21724005: length 2
  BOTTOM w0.3: C339.2 21.87,51.79 U302.23
N21724007: length 36.9
  TOP w0.4: L314.1 L304.1
  TOP w0.5: 21.6,46.5 v1(21.6,44.98) v1(21.6,44.38) 21.9,44.38 ; 21.6,46.5 21.9,46.2 ; 21.6,46.5 20.55,47.55 ; 21.9,44.38 v1(22.2,44.38) v1(22.2,44.98) 22.2,45.9 21.9,46.2 ; 21.9,44.38 21.9,46.2
  BOTTOM w0.3: C339.1 21.77,50.79 U302.21 ; C344.1 26.04,47.71 25.6,48.15 25.6,49.45 25.37,49.68 U302.18
  BOTTOM w0.5: v1(22.2,44.98) 22.2,45.74 22.49,46.03 ; v1(22.2,44.98) v1(21.6,44.98) ; v1(22.2,44.98) v1(22.2,44.38) 21.9,44.38 ; v1(21.6,44.98) 21.6,46.56 21.78,46.74 ; v1(21.6,44.98) v1(21.6,44.38) 21.9,44.38 ; C344.1 26.21,46.26 R324.1 ; 21.9,44.38 21.9,46.62 ; C339.1 21.78,50.72 R322.2 21.78,46.74 ; 21.78,46.74 21.9,46.62 ; 21.9,46.62 22.49,46.03 ; 22.49,46.03 22.51,46.05 25.7,46.05 R324.1 ; 22.49,46.03 22.77,45.75 25.7,45.75 R324.1
N21724126: length 1.3
  BOTTOM w0.5: R322.1 C343.2
N21724132: length 4.5
  BOTTOM w0.2: U302.13 27.87,49.13 28.15,48.85 28.15,47.03 T303.1
N21724134: length 1.6
  BOTTOM w0.2: U302.14 27.37,48.67 R323.2
N21724136: length 4.2
  BOTTOM w0.2: U302.15 26.87,47.33 27,47.2 27,46.55 T304.1
N21724138: length 1.6
  BOTTOM w0.3: U302.16 26.37,48.77 C344.2
N21724244: length 1.5
  BOTTOM w0.5: C345.2 R324.2
N21735247: length 1.8
  TOP w0.1: UNK4U9.K2 v1(39.95,43.6)
  BOTTOM w0.1: UNK4C26.2 v1(39.95,43.6)
N21735401: length 1.8
  TOP w0.1: UNK4U9.R5 v1(42,41.1)
  BOTTOM w0.1: v1(42,41.1) 41.8,40.9 UNK4R17.2
N21775203: length 4.5
  BOTTOM w0.1: UNK5R71.1 85.55,11.25 85.17,10.88 85.17,10.61 85.94,9.85 86.55,9.85 87.03,9.38 87.03,8.46 87.18,8.3 J813.1
N21775223: length 4.5
  BOTTOM w0.1: J813.2 86.68,8.3 86.8,8.42 86.8,9.28 86.46,9.62 85.84,9.62 84.95,10.52 84.95,10.85 84.55,11.25 UNK5R72.1
N21775243: length 4.5
  BOTTOM w0.1: UNK5R73.1 83.1,10.8 84.15,9.75 84.7,9.75 85.68,8.77 J813.4
N21775263: length 4.8
  BOTTOM w0.1: J813.5 85.18,8.67 84.4,9.45 84.05,9.45 82.45,11.05 82.2,11.05 UNK5R74.1
N21775283: length 8
  BOTTOM w0.1: UNK5R75.1 82,14 81.5,13.5 81.5,10.95 81.65,10.8 82.4,10.8 84.68,8.52 J813.6
N21778072: length 4.2
  TOP w0.102: U1.A4 59.74,51.31 59.84,51.41 59.84,52.56 58.72,53.68 T109.1
N21778081: length 6.5
  TOP w0.102: T110.1 58.73,55.88 59.28,55.32 59.28,53.44 60.06,52.66 60.06,50.45 U1.B5
N21778090: length 8.4
  TOP w0.1: U1.B2 58.44,50.29 58.11,50.62 58.11,51.11 56.39,52.83 56.39,56.49 T111.1
N21778099: length 9.4
  TOP w0.1: U1.A2 58.42,50.79 58.42,51.12 56.59,52.95 56.59,58.21 56.08,58.72 T112.1
N21778148: length 10.2
  TOP w0.102: U1.A3 59.08,50.78 59.08,52.28 57.55,53.8 57.55,59.8 T113.1
N21778157: length 11.3
  TOP w0.1: U1.B3 58.76,50.45 58.76,51.09 56.79,53.06 56.79,58.81 T114.1
N21778166: length 6
  TOP w0.1: U1.A1 57.79,51.13 56.18,52.73 56.18,55.28 T115.1
N21778175: length 6.9
  TOP w0.1: T116.1 55.98,54.06 55.98,52.63 57.43,51.18 57.43,50.62 57.61,50.45 57.89,50.45 58.11,50.22 58.11,50.02 58.35,49.79 58.77,49.79 U1.C3
N21778255: length 6.4
  TOP w0.1: T120.1 63.73,55.73 63.73,51.12 63.97,50.88 63.97,50.45 U1.B10
N21800110: length 28.6
  BOTTOM w0.1: R226.1 R225.1 80.65,64.05 75.85,64.05 75.35,64.55 75.35,68.95 73.4,70.9 66.4,70.9 65,69.5 61.95,69.5 61.02,68.58
  BOTTOM w0.3: 61.02,68.58 T310.1
N21860313: length 4.5
  BOTTOM w0.2: R228.2 84.73,56.25 C252.2 84.74,55.95 85.39,55.3 U201.8
N21864534: length 4.5
  BOTTOM w0.2: R230.2 C254.2 84.74,34.01 85.39,33.36 U202.8
N21877006: length 4.5
  BOTTOM w0.2: R326.2 C350.2 32.31,29.19 31.66,29.84 U301.8
N21880362: length 4.5
  BOTTOM w0.2: R328.2 33.44,50.84 C352.2 32.31,51.14 31.66,51.79 U302.8
N21888872: length 4.1
  BOTTOM w0.25: R17.2 R16.2 37.95,11.85 37,12.8 Q3.3
N21888995: length 5.7
  TOP w0.25: R19.2 R18.2 v1(35.6,5.09)
  BOTTOM w0.25: v1(35.6,5.09) 35.6,6 37.1,7.5 Q2.3
N21888998: length 1.6
  BOTTOM w0.25: Q2.1 R16.1
N21889394: length 1.5
  BOTTOM w0.25: Q3.1 R15.1
N21890397: length 3.9
  BOTTOM w0.1: R332.2 R329.2 80.05,30.5 Q4.3
N21890399: length 2.5
  BOTTOM w0.1: Q5.3 74.75,30.2 R331.2 R330.2
N21890429: length 2.3
  BOTTOM w0.1: R332.1 77.25,27.85 Q5.1
N21890459: length 1.5
  BOTTOM w0.2: Q4.1 81.35,27.75 R333.1
N21892579: length 9.9
  TOP w0.1: U1.G15 66.89,46.87 v2(67.16,47.13)
  BOTTOM w0.1: v2(67.16,47.13) 67.32,47.13 68.2,48.01 72.17,48.01 75.08,45.1 R343.1
N21892587: length 7.2
  TOP w0.1: R344.1 74.7,48.05 73.9,48.05 73.55,47.7 68.9,47.7 68.72,47.52 U1.F17
N21892603: length 13.6
  TOP w0.1: v1(78.25,50.33) 78.25,49.95 76.55,48.25 73.8,48.25 73.45,47.9 68.55,47.9 68.5,47.85 67.87,47.85 U1.F16
  BOTTOM w0.1: R103.1 79.15,49.25 78.25,50.15 v1(78.25,50.33)
N21892620: length 13.7
  TOP w0.102: v2(67.22,47.85) U1.F15
  BOTTOM w0.1: R104.1 78.75,50.7 75.2,50.7 72.94,48.44 67.99,48.44 67.4,47.85 v2(67.22,47.85)
N21892674: length 8
  TOP w0.1: U1.H16 67.66,46.22 67.98,45.9 68.86,45.9 69.04,45.72 74.43,45.72 R107.1
N21892682: length 1.9
  TOP w0.1: U1.G17 69.98,46.87 R108.1
N21892690: length 8.1
  TOP w0.1: v1(74.1,47.65) 73.95,47.5 69.15,47.5 68.85,47.2 67.87,47.2 U1.G16
  BOTTOM w0.1: v1(74.1,47.65) 74.1,47.55 74.85,46.8 R109.1
N21892698: length 8.8
  TOP w0.1: U1.G14 v2(66.57,47.2)
  BOTTOM w0.1: R110.1 73.7,48.75 73.19,48.24 68.12,48.24 67.37,47.49 66.86,47.49 v2(66.57,47.2)
N22017810: length 20.7
  TOP w0.1: v1(88.6,17.7) 88.38,17.48 88.38,17.17 87.85,16.65 86.65,16.65 86.2,16.2 UNK5R84.1
  BOTTOM w0.1: v1(88.6,17.7) 88.35,17.45 88.35,11.78 90.83,9.3 93.38,9.3 95.38,7.31 95.38,5.52 95.6,5.3 J814.2
N22017884: length 25.2
  TOP w0.1: UNK5R83.1 83.35,18.45 87.1,18.45 87.8,19.15 v1(88.5,19.15)
  BOTTOM w0.1: J814.4 94.3,7.2 92.95,8.55 90.45,8.55 87.45,11.55 87.45,18.75 87.85,19.15 v1(88.5,19.15)
N22060831: length 20.3
  TOP w0.1: v1(87.9,17.7) 88.15,17.45 88.15,17.27 87.76,16.88 86.63,16.88 86.2,17.3 UNK5R85.1
  BOTTOM w0.1: v1(87.9,17.7) 88.12,17.48 88.12,11.69 90.74,9.07 93.29,9.07 95.15,7.21 95.15,5.5 94.95,5.3 J814.3
N22094186: length 3
  BOTTOM w0.6: C267.2 R235.2 C268.1
N22094236: length 3
  BOTTOM w0.6: C269.2 R236.1 C270.1
N22143757: length 1.5
  TOP w0.3: C5.1 11.5,12.84 U2.1
N22143759: length 5
  TOP w0.3: v1(9.85,11.35) C5.2
  BOTTOM w0.3: v1(14.1,11.35) v1(9.85,11.35)
N22143887: length 1.7
  TOP w0.25: U2.8 11.49,18.45 R21.2
N22143889: length 4.4
  TOP w0.25: U2.5 16.01,17.95 R11.2 C10.1 R10.1
N22143938: length 4
  TOP w0.25: U2.6 v1(14.13,19.5)
  BOTTOM w0.25: v1(14.13,19.5) 12.95,18.31 C25.2 C24.2
N22143998: length 1.3
  BOTTOM w0.25: C24.1 10.7,18.05 R22.2

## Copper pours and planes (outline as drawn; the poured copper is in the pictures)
GND on TOP: 2,0.5 0.94,0.94 0.5,2 0.5,61.75 0.94,62.81 2,63.25 4,63.25 8.77,65.23 10.75,70 10.75,74 10.9,74.35 11.25,74.5 85.25,74.5 85.6,74.35 85.75,74 85.75,70 89.21,64.1 96.05,64.26 96.05,63 98,63 98,64.75 96.74,64.75 98.48,66.87 99.23,69.5 99.25,69.5 99.25,74 99.4,74.35 99.75,74.5 115,74.5 116.06,74.06 116.5,73 116.5,23 116.06,21.94 115,21.5 101,21.5 99.94,21.06 99.5,20 99.5,2 99.06,0.94 98,0.5 77.25,0.5 76.9,0.65 76.75,1 76.75,4.5 70,11.25 63.25,4.5 63.25,1 63.1,0.65 62.75,0.5 ; 20 cut-outs
VCC5V on TOP: 17.85,7.65 17.85,3.9 18.15,3.6 24.65,3.6 25.1,4.05 25.1,7.65
VCC5V on TOP: 35.15,10.44 33.31,10.44 33.16,10.29 31.51,10.29 31.51,9.79 31.91,9.79 33.32,8.37 35.22,8.37 35.4,8.55 35.4,10.19
VCC5V on BOTTOM: 44.7,10.5 44.7,9.25 44.85,9.1 46.25,9.1 47.7,10.55 48.65,10.55 48.65,11 48.6,11.05 47.35,11.05 47.2,11.2 45.4,11.2
VCC5V on MID2(L3): 26.8,10.2 56.55,10.2 56.55,8.6 56.35,8.4 29.8,8.4 25,3.6 23.2,3.6 23,3.8 23,6.4
VCC_3.3V on MID2(L3): 38.05,28.2 37.8,28.45 37.8,29.35 44.55,36.1 44.55,38.85 42.75,40.65 42.75,42.25 42.85,42.35 43.55,42.35 44.05,42.85 44.05,45.3 42.45,46.9 42.45,54.7 38.7,58.45 38.7,59.2 38.85,59.35 48.4,59.35 50.35,57.4 54.5,57.4 55.3,56.6 62.4,56.6 63.35,57.55 67.8,57.55 69.7,55.65 77.55,55.65 78.95,54.25 78.95,53.85 49.7,53.85 48,52.15 48,31.25 44.95,28.2
VDD_EE on TOP: 38.25,20.65 38.25,18.2 42.4,18.2 42.95,17.65 42.95,15.95 43.5,15.4 44.55,15.4 44.65,15.5 44.65,21.15 44.4,21.4 39,21.4
VDD_EE on MID2(L3): 43.55,15.55 43.55,26.35 48.25,31.05 48.25,43.7 50.55,46 52,46 52.15,45.85 52.15,43.9 50.5,42.25 50.5,30.1 45.25,24.85 45.25,15.4 43.7,15.4
VDDAO_3.3V on TOP: 27.51,20.64 27.11,20.24 27.11,17.94 32.71,17.94 32.91,17.74 32.91,14.84 33.11,14.64 34.11,14.64 34.36,14.89 34.36,20.34 34.06,20.64
VDDAO_3.3V on MID2(L3): 32.8,21.65 29.65,24.8 27.35,24.8 27.2,24.95 27.2,25.25 27.4,25.45 32.25,25.45 33.8,27 33.8,31.1 29.8,35.1 29.8,36 31.25,37.45 31.25,42.85 27.1,47 27.1,47.4 30.05,50.35 30.05,56.05 27.2,58.9 27.2,60.8 28.85,62.45 79,62.45 82.85,58.6 86.2,58.6 86.45,58.35 86.45,57.5 85.7,56.75 79.35,56.75 78.1,58 64.45,58 64.2,57.75 56,57.75 55.4,58.35 54.55,58.35 54,57.8 50.6,57.8 48.55,59.85 36.3,59.85 35.35,58.9 35.35,37.25 37.1,35.5 37.1,34.6 35.9,33.4 35.9,27.05 37.3,25.65 37.3,14.1 37.2,14.1 36.8,14.5 33.1,14.5 32.8,14.8
VDDCPU on BOTTOM (solid shape): 52.4,50.8 52.4,48.54 53.09,47.85 55.63,47.85 55.88,47.6 55.88,46.39 52.39,46.39 50.7,48.08 50.7,50.8 50.85,50.95 52.25,50.95
VDDCPU on BOTTOM: 53.1,20.6 53.1,18.5 48.7,18.5 48.14,17.94 48.15,15 47.95,14.8 46.6,14.8 46.45,14.95 46.44,21.1 46.74,21.4 52.3,21.4
VDDCPU on MID2(L3): 45.65,15.05 45.65,24.7 50.8,29.85 50.8,42.25 52.3,43.75 52.3,48.05 50.7,49.65 50.7,51 51.05,51.35 52.55,51.35 54.7,49.2 54.7,43.4 53.65,42.35 53.65,28.4 47.55,22.3 47.55,14.95 47.4,14.8 45.9,14.8
VDDQ1.35V on BOTTOM (solid shape): 57.45,39.57 55.59,37.71 54.06,37.71 53.75,38.02 53.75,39.27 54,39.52 55.5,39.52 57.45,41.48
VDDQ1.35V on TOP: 54.3,13.5 55.2,13.5 55.35,13.65 55.35,19.55 54.7,20.2 49.65,20.2 49.65,18.6 53.4,18.6 53.65,18.35 53.65,14.15
VDDQ1.35V on MID2(L3): 54.05,13.85 54.4,13.5 61.1,13.5 72.05,24.45 72.05,39.25 67.25,44.05 55.9,44.05 54.05,42.2
Net_149 on TOP, BOTTOM, MID1(L2), MID2(L3): -4.5,0.5 -5.56,0.94 -6,2 -6,150 -5.56,151.06 -4.5,151.5 -4.25,151.5 13,151.5 14.06,151.06 14.5,150 14.5,133.5 2,133.5 -1.18,132.18 -2.5,129 -2.5,2 -2.94,0.94 -4,0.5
Net_149 on TOP, BOTTOM, MID1(L2), MID2(L3): 121.5,151.5 122.56,151.06 123,150 123,2 122.56,0.94 121.5,0.5 121.25,0.5 104,0.5 102.94,0.94 102.5,2 102.5,18.5 115,18.5 118.18,19.82 119.5,23 119.5,150 119.94,151.06 121,151.5
OUT1A_B_LF on TOP: 104.1,24.7 107.6,24.7 107.75,24.85 107.75,31.55 107.6,31.7 104.1,31.7 103.95,31.55 103.95,24.85
OUT1A_B_LF on BOTTOM: 102.6,31.7 102.6,25.1 105.6,25.1 105.9,25.4 105.9,30.8 105,31.7
OUT1A_B_LW on TOP: 104.1,46.7 107.6,46.7 107.75,46.85 107.75,53.55 107.6,53.7 104.1,53.7 103.95,53.55 103.95,46.85
OUT1A_B_LW on BOTTOM: 105.3,46.2 105.3,53.4 105,53.7 102.6,53.7 102.6,43.6 102.85,43.35 104.1,43.35 104.4,43.65 104.4,45.3
OUT1A_B_RF on TOP: 9.45,53.45 12.9,53.45 13.05,53.6 13.05,60.25 12.9,60.4 9.45,60.4 9.3,60.25 9.3,53.6
OUT1A_B_RF on BOTTOM: 4.3,39.2 6.1,39.2 6.3,39.4 6.3,48.2 11.5,53.4 13.3,53.4 13.4,53.5 14.5,53.5 14.5,55.2 9,55.2 4,50.2 4,39.5
OUT1A_B_RW on TOP: 9.5,31.5 12.9,31.5 13.05,31.65 13.05,38.3 12.85,38.5 9.5,38.5 9.3,38.3 9.3,31.7
OUT1A_B_RW on BOTTOM: 11.8,31.7 12,31.5 14.4,31.5 14.4,38 12.2,38 12.2,35.8 11.8,35.4
OUT2A_B_LF on TOP: 104.1,32.5 107.6,32.5 107.75,32.65 107.75,39.35 107.6,39.5 104.1,39.5 103.95,39.35 103.95,32.65
OUT2A_B_LF on BOTTOM: 102.6,32.5 102.6,39.1 103.3,39.1 104.6,37.8 104.6,34.2 105.2,33.6 105.2,32.8 104.9,32.5
OUT2A_B_LW on TOP: 104.1,54.5 107.6,54.5 107.75,54.65 107.75,61.35 107.6,61.5 104.1,61.5 103.95,61.35 103.95,54.65
OUT2A_B_LW on BOTTOM: 105.7,45.95 105.7,53.9 105.1,54.5 102.4,54.5 102.4,56.3 107.2,56.3 107.6,55.9 107.6,44.65 106.35,43.4 104.8,43.4 104.8,45.05
OUT2A_B_RF on TOP: 9.45,45.65 12.9,45.65 13.05,45.8 13.05,52.5 12.9,52.65 9.45,52.65 9.3,52.5 9.3,45.8
OUT2A_B_RF on BOTTOM: 8.5,39.2 6.9,39.2 6.7,39.4 6.7,48 11.3,52.6 14.4,52.6 14.4,49.3 14.2,49.1 10.7,49.1 8.7,47.1 8.7,39.4
OUT2A_B_RW on TOP: 9.3,23.7 12.7,23.7 13.05,24.05 13.05,30.6 12.95,30.7 9.55,30.7 9.3,30.45
OUT2A_B_RW on BOTTOM: 11.8,24.2 14.3,24.2 14.4,24.3 14.4,30.7 12,30.7 11.8,30.5
PWR_24V on TOP: 31.95,3.75 57.7,3.75 59.85,5.9 61.25,5.9 61.4,5.75 61.4,4.3 58.6,1.5 31.95,1.5 31.75,1.7 31.75,3.55
PWR_24V on TOP: 78.55,13.45 78.55,12.85 81.1,10.3 81.1,7.2 77.5,7.2 77.5,8.15 74.4,11.25 74.4,13.3 74.55,13.45
PWR_24V on TOP: 47.6,67.75 47.6,63.25 37.8,63.25 37.8,67.75 39.15,69.1 46.25,69.1
PWR_24V on TOP: 13.2,11.8 13.2,2.3 10.8,2.3 10.5,2.6 10.5,7.5 12.6,9.6 12.6,11.8
PWR_24V on TOP: 68.7,67.2 68.7,63.7 69.3,63.1 80.1,63.1 80.7,63.7 80.7,67.2 80.1,67.8 69.3,67.8
PWR_24V on BOTTOM: 34,3.5 34,2 33.5,1.5 27.5,1.5 25.5,3.5 25.5,13 22.5,16 22.5,18 23,18.5 26.5,18.5 29.5,15.5 29.5,6 31.5,4 33.5,4
PWR_24V on BOTTOM: 59,3.85 58.8,4.05 58.8,8.6 64.55,14.35 72.85,14.35 73.85,15.35 73.85,22.4 76.55,25.1 83.55,25.1 86.05,22.6 89.05,22.6 89.8,21.85 92.45,21.85 92.65,21.65 92.65,20.25 92.5,20.1 89.15,20.1 88.35,20.9 85.4,20.9 83,23.3 77.8,23.3 76.1,21.6 76.1,11.2 76,11.1 74.45,11.1 73.75,11.8 66.1,11.8 61.45,7.15 61.45,4.05 61.25,3.85
PWR_24V on MID2(L3): 33.5,4 26,4 25,3 23,3 21.5,4.5 10.5,4.5 10,4 10,2 10.5,1.5 33.5,1.5 34,2 34,3.5
PWR_24V on MID2(L3): 17.95,62.1 25.1,69.25 44.35,69.25 44.65,68.95 44.65,63.75 44.45,63.55 28.1,63.55 26.25,61.7 26.25,17.4 25.1,16.25 18.5,16.25 17.95,16.8
PWR_24V on MID2(L3): 90.9,20.3 90.9,55.5 86.5,59.9 82.75,59.9 79.25,63.4 71.6,63.4 71.2,63.8 71.2,67.15 71.8,67.75 84.3,67.75 90.05,62 94.85,62 98.25,58.6 98.25,20.85 97.5,20.1 91.1,20.1
N21492258 on BOTTOM: 53,17.3 53,15.66 51.09,13.75 51.09,12.1 50.49,11.5 49.5,11.5 49.5,14.8 48.75,15.55 48.75,17.3
N21499562 on TOP: 41.6,11.5 41.6,14.2 42.35,14.95 42.35,17 38.35,17 38.35,15.65 40,14 40,12.1 40.6,11.5
N21500929 on TOP: 52.3,11.5 52.3,16.45 52.25,16.5 49.75,16.5 49.75,14.95 50.7,14 50.7,12.1 51.3,11.5
N21506095 on TOP: 27.21,16.34 27.21,14.44 28.26,14.44 29.71,12.99 29.71,11.34 30.31,10.74 31.31,10.74 31.31,13.84 32.61,15.14 32.61,16.34
N21714583 on TOP: 94.75,45.15 97.6,45.15 97.75,45.3 97.75,50.35 97.6,50.5 94.75,50.5 94.6,50.35 94.6,45.3
N21715058 on TOP: 94.75,57.7 97.6,57.7 97.75,57.85 97.75,62.95 97.6,63.1 94.75,63.1 94.6,62.95 94.6,57.85
N21715401 on BOTTOM: 112.1,30.6 112.1,33.6 103.9,41.8 103.9,42.4 102.6,42.4 102.6,40.6 105.3,37.9 105.3,37.6 109.7,33.2 109.7,30.7 110.4,30 111.5,30
N21715403 on BOTTOM: 104.85,42.5 104.85,41.45 112.6,33.7 112.6,30.3 111.8,29.5 110.6,29.5 110.3,29.2 110.3,27.8 110.6,27.5 113.5,27.5 114.8,28.8 114.8,34.2 106.5,42.5
